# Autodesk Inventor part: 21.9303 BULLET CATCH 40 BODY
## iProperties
Created: 2012-06
Part Number: 21.9303 BULLET CATCH 40 BODY
Document SubType Name: Modeling
Designer: Administrator
Density: 1.06 g/cm^3
Material: ABS Plastic
Mass: 12.3233 g
Surface Area: 102.481 cm^2
Volume: 11.6257 cm^3
Author: Administrator
